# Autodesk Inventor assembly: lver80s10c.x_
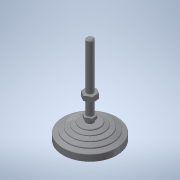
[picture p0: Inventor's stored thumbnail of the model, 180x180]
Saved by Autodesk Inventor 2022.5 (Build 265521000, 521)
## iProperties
Part Number: lver80s10c.x_
Material: 一般
Document SubType Name: Assembly
Designer: ImaoCorp
Sending System: SOLIDWORKS 2017-2017317
MC: AMD64
MC_MODEL: Intel64 Family 6 Model 60 Stepping 3, GenuineIntel
OS: Windows_NT
FRU: Parasolid Version 29.0, build 201,  4-17-2017
FORMAT: text
GUISE: transmit
KEY: lver80s10c
FILE: lver80s10c.x_t
DATE: Mon Jul 01 18:28:13 2019
Author: ImaoCorp
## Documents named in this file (3)
- X:\14_SW2022-Inv2022\00_全2023-1023新製品(TCC)まで\l\lver80s10c\LVER80S10C.iam
- X:\14_SW2022-Inv2022\00_全2023-1023新製品(TCC)まで\l\lver80s10c\lver80s10c_01.ipt
- X:\14_SW2022-Inv2022\00_全2023-1023新製品(TCC)まで\l\lver80s10c\lver80s10c_02.ipt
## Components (2 placed, 2 different names)
1. lver80s10c_01
2. lver80s10c_02
